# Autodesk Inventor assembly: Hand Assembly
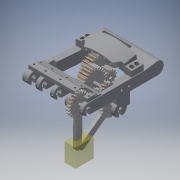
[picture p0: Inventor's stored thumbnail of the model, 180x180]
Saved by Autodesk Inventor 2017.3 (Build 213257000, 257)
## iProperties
Created: 2016-09
Part Number: Hand Assembly
Document SubType Name: Assembly
Designer: cmcdona
Author: cmcdona
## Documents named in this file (22)
- C:\Users\Tim_G\OneDrive - McMaster University\Documents\Documents\Books\McMaster First Year Courses\Winter Engineering 1C03\Project\Project Files (Prosthetic Frame Assembly)\Hand Assembly.iam
- C:\Users\Tim_G\OneDrive - McMaster University\Documents\Documents\Books\McMaster First Year Courses\Winter Engineering 1C03\Project\Project Files (Prosthetic Frame Assembly)\Hand - Frame.ipt
- C:\Users\Tim_G\OneDrive - McMaster University\Documents\Documents\Books\McMaster First Year Courses\Winter Engineering 1C03\Project\Project Files (Prosthetic Frame Assembly)\Hand - Digit 4.ipt
- C:\Users\Tim_G\OneDrive - McMaster University\Documents\Documents\Books\McMaster First Year Courses\Winter Engineering 1C03\Project\Project Files (Prosthetic Frame Assembly)\Hand - Digit 0-1.ipt
- C:\Users\Tim_G\OneDrive - McMaster University\Documents\Documents\Books\McMaster First Year Courses\Winter Engineering 1C03\Project\Project Files (Prosthetic Frame Assembly)\Hand - Distal Bridge.ipt
- C:\Users\Tim_G\OneDrive - McMaster University\Documents\Documents\Books\McMaster First Year Courses\Winter Engineering 1C03\Project\Project Files (Prosthetic Frame Assembly)\Hand - Digit 2-3.ipt
- C:\Users\Tim_G\OneDrive - McMaster University\Documents\Documents\Books\McMaster First Year Courses\Winter Engineering 1C03\Project\Project Files (Prosthetic Frame Assembly)\Hand - Proximal Bridge.ipt
- C:\Users\Tim_G\OneDrive - McMaster University\Documents\Documents\Books\McMaster First Year Courses\Winter Engineering 1C03\Project\Project Files (Prosthetic Frame Assembly)\Hand - Functional Workspace.ipt
- C:\Users\Tim_G\OneDrive - McMaster University\Documents\Documents\Books\McMaster First Year Courses\Winter Engineering 1C03\Project\Project Files (Prosthetic Frame Assembly)\Input Motor.ipt
- C:\Users\Tim_G\OneDrive - McMaster University\Documents\Documents\Books\McMaster First Year Courses\Winter Engineering 1C03\Project\Project Files (Prosthetic Frame Assembly)\Hand Assembly\Design Accelerator\Spur Gears1.iam
- C:\Users\Tim_G\OneDrive - McMaster University\Documents\Documents\Books\McMaster First Year Courses\Winter Engineering 1C03\Project\Project Files (Prosthetic Frame Assembly)\Hand Assembly\Design Accelerator\Spur Gear11.ipt
- C:\Users\Tim_G\OneDrive - McMaster University\Documents\Documents\Books\McMaster First Year Courses\Winter Engineering 1C03\Project\Project Files (Prosthetic Frame Assembly)\Hand Assembly\Design Accelerator\Spur Gear21.ipt
- C:\Users\Tim_G\OneDrive - McMaster University\Documents\Documents\Books\McMaster First Year Courses\Winter Engineering 1C03\Project\Project Files (Prosthetic Frame Assembly)\Hand Assembly\Design Accelerator\Spur Gears2.iam
- C:\Users\Tim_G\OneDrive - McMaster University\Documents\Documents\Books\McMaster First Year Courses\Winter Engineering 1C03\Project\Project Files (Prosthetic Frame Assembly)\Rod1.ipt
- C:\Users\Tim_G\OneDrive - McMaster University\Documents\Documents\Books\McMaster First Year Courses\Winter Engineering 1C03\Project\Project Files (Prosthetic Frame Assembly)\Hand Assembly\Design Accelerator\Spur Gears3.iam
- C:\Users\Tim_G\OneDrive - McMaster University\Documents\Documents\Books\McMaster First Year Courses\Winter Engineering 1C03\Project\Project Files (Prosthetic Frame Assembly)\Hand Assembly\Design Accelerator\Spur Gear13.ipt
- C:\Users\Tim_G\OneDrive - McMaster University\Documents\Documents\Books\McMaster First Year Courses\Winter Engineering 1C03\Project\Project Files (Prosthetic Frame Assembly)\Hand Assembly\Design Accelerator\Spur Gear23.ipt
- C:\Users\Tim_G\OneDrive - McMaster University\Documents\Documents\Books\McMaster First Year Courses\Winter Engineering 1C03\Project\Project Files (Prosthetic Frame Assembly)\Hand Assembly\Design Accelerator\Spur Gear12.ipt
- C:\Users\Tim_G\OneDrive - McMaster University\Documents\Documents\Books\McMaster First Year Courses\Winter Engineering 1C03\Project\Project Files (Prosthetic Frame Assembly)\Hand Assembly\Design Accelerator\Spur Gear22.ipt
- C:\Users\Tim_G\OneDrive - McMaster University\Documents\Documents\Books\McMaster First Year Courses\Winter Engineering 1C03\Project\Project Files (Prosthetic Frame Assembly)\Hand Assembly\Design Accelerator\Spur Gears5.iam
- C:\Users\Tim_G\OneDrive - McMaster University\Documents\Documents\Books\McMaster First Year Courses\Winter Engineering 1C03\Project\Project Files (Prosthetic Frame Assembly)\Hand Assembly\Design Accelerator\Spur Gears6.iam
- C:\Users\Tim_G\OneDrive - McMaster University\Documents\Documents\Books\McMaster First Year Courses\Winter Engineering 1C03\Project\Project Files (Prosthetic Frame Assembly)\Hand Assembly\Design Accelerator\Spur Gear16.ipt
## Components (27 placed, 12 different names)
1. Hand - Frame:1 — Flush:1, Flush:2, Mate:1, Mate:2, Flush:3, Mate:3, Mate:16, Mate:17, Mate:18, Mate:22, Mate:24, Mate:25
2. Hand - Digit 4:1 — Flush:1, Flush:2, Mate:1, Mate:4, Mate:5
3. Hand - Digit 0-1:1 — Mate:2, Flush:3, Mate:3, Mate:6, Mate:19, Mate:20, Mate:21, Mate:45, Mate:48, Mate:49, Mate:51
4. Hand - Distal Bridge:1 — Mate:4, Mate:5, Mate:6, Mate:7, Mate:8, Mate:9, Mate:10, Mate:11, Mate:12, Mate:13, Mate:14, Mate:15, Mate:53
5. Hand - Digit 2-3:1 — Mate:7, Mate:8, Mate:9
6. Hand - Digit 2-3:2 — Mate:10, Mate:11, Mate:12
7. Hand - Digit 2-3:3 — Mate:13, Mate:14, Mate:15
8. Hand - Proximal Bridge:1 — Mate:16, Mate:17, Mate:18
9. Hand - Functional Workspace:1 — Mate:19, Mate:20, Mate:21
10. Input Motor:1 — Mate:22, Mate:24, Mate:25, Mate:39, Mate:52, Flush:14
11. Spur Gears:1 [sub-assembly] — Mate:52, Flush:14
12. Spur Gear1:1 — Tangent:1, Mate:39, Flush:15
13. Spur Gear2:1 — Mate:26, Tangent:1, Mate:40, Flush:15
14. Spur Gears:2 [sub-assembly]
15. Spur Gear1:3 — Mate:34, Tangent:4, Flush:8
16. Spur Gear2:3 — Mate:35, Tangent:4, Flush:8
17. Rod1:1 — Mate:34, Mate:40
18. Rod1:2 — Mate:32, Mate:35, Mate:44, Mate:50
19. Spur Gears:3 [sub-assembly] — Mate:32
20. Spur Gear1:2 — Flush:5, Mate:44, Flush:11, Tangent:5, Tangent:6
21. Spur Gear2:2 — Flush:5, Mate:49, Mate:50, Tangent:7, Mate:53
22. Spur Gear2:4 — Mate:45, Flush:11, Tangent:5, Flush:13
23. Spur Gears:4 [sub-assembly]
24. Rod1:3 — Mate:48
25. Spur Gears:5 [sub-assembly]
26. Spur Gear1:4 — Tangent:6, Flush:13, Tangent:7
27. Rod1:4 — Mate:51
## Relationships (52: Mate 38, Flush 9, Tangent 5)
- Flush:1: Hand - Frame:1 ↔ Hand - Digit 4:1
- Flush:2: Hand - Frame:1 ↔ Hand - Digit 4:1
- Mate:1: Hand - Frame:1 ↔ Hand - Digit 4:1
- Mate:2: Hand - Frame:1 ↔ Hand - Digit 0-1:1
- Flush:3: Hand - Frame:1 ↔ Hand - Digit 0-1:1
- Mate:3: Hand - Frame:1 ↔ Hand - Digit 0-1:1
- Mate:4: Hand - Digit 4:1 ↔ Hand - Distal Bridge:1
- Mate:5: Hand - Digit 4:1 ↔ Hand - Distal Bridge:1
- Mate:6: Hand - Digit 0-1:1 ↔ Hand - Distal Bridge:1
- Mate:7: Hand - Distal Bridge:1 ↔ Hand - Digit 2-3:1
- Mate:8: Hand - Distal Bridge:1 ↔ Hand - Digit 2-3:1
- Mate:9: Hand - Distal Bridge:1 ↔ Hand - Digit 2-3:1
- Mate:10: Hand - Distal Bridge:1 ↔ Hand - Digit 2-3:2
- Mate:11: Hand - Distal Bridge:1 ↔ Hand - Digit 2-3:2
- Mate:12: Hand - Distal Bridge:1 ↔ Hand - Digit 2-3:2
- Mate:13: Hand - Distal Bridge:1 ↔ Hand - Digit 2-3:3
- Mate:14: Hand - Distal Bridge:1 ↔ Hand - Digit 2-3:3
- Mate:15: Hand - Distal Bridge:1 ↔ Hand - Digit 2-3:3
- Mate:16: Hand - Frame:1 ↔ Hand - Proximal Bridge:1
- Mate:17: Hand - Frame:1 ↔ Hand - Proximal Bridge:1
- Mate:18: Hand - Frame:1 ↔ Hand - Proximal Bridge:1
- Mate:19: Hand - Digit 0-1:1 ↔ Hand - Functional Workspace:1
- Mate:20: Hand - Digit 0-1:1 ↔ Hand - Functional Workspace:1
- Mate:21: Hand - Digit 0-1:1 ↔ Hand - Functional Workspace:1
- Mate:22: Hand - Frame:1 ↔ Input Motor:1
- Mate:24: Hand - Frame:1 ↔ Input Motor:1
- Mate:25: Hand - Frame:1 ↔ Input Motor:1
- Mate:26: Spur Gear2:1
- Tangent:1: Spur Gear1:1 ↔ Spur Gear2:1
- Mate:32: Rod1:2 ↔ Spur Gears:3
- Mate:34: Spur Gear1:3 ↔ Rod1:1
- Mate:35: Spur Gear2:3 ↔ Rod1:2
- Flush:5: Spur Gear1:2 ↔ Spur Gear2:2
- Mate:39: Input Motor:1 ↔ Spur Gear1:1
- Tangent:4: Spur Gear1:3 ↔ Spur Gear2:3
- Flush:8: Spur Gear1:3 ↔ Spur Gear2:3
- Mate:40: Spur Gear2:1 ↔ Rod1:1
- Mate:44: Rod1:2 ↔ Spur Gear1:2
- Mate:45: Hand - Digit 0-1:1 ↔ Spur Gear2:4
- Flush:11: Spur Gear1:2 ↔ Spur Gear2:4
- Tangent:5: Spur Gear1:2 ↔ Spur Gear2:4
- Mate:48: Hand - Digit 0-1:1 ↔ Rod1:3
- Mate:49: Hand - Digit 0-1:1 ↔ Spur Gear2:2
- Mate:50: Rod1:2 ↔ Spur Gear2:2
- Tangent:6: Spur Gear1:2 ↔ Spur Gear1:4
- Flush:13: Spur Gear2:4 ↔ Spur Gear1:4
- Tangent:7: Spur Gear2:2 ↔ Spur Gear1:4
- Mate:51: Hand - Digit 0-1:1 ↔ Rod1:4
- Mate:52: Input Motor:1 ↔ Spur Gears:1
- Flush:14: Input Motor:1 ↔ Spur Gears:1
- Flush:15: Spur Gear1:1 ↔ Spur Gear2:1
- Mate:53: Hand - Distal Bridge:1 ↔ Spur Gear2:2
